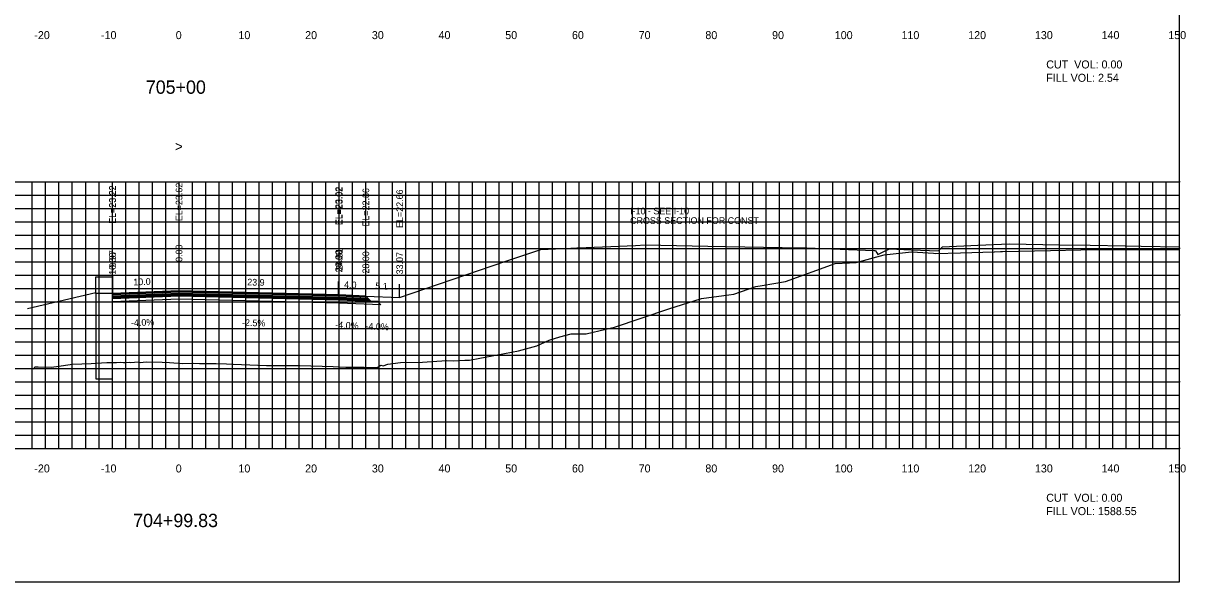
# Model space of a CAD drawing. Extents: x 1797518 to 1804843, y 248068 to 251132.
# Drawn here: x 1803287.6 to 1803461.9, y 250079.4 to 250163.2 of the extents above; entities that cross this region are included whole.
import ezdxf

# ---------------------------------------------------------------- set-up
doc = ezdxf.new("R2010")
doc.units = 0
for name, color, linetype in [('1', 7, 'Continuous'), ('10', 7, 'Continuous'), ('3', 7, 'Continuous'), ('4', 7, 'Continuous'), ('60', 7, 'Continuous'), ('ANNO-TXT', 7, 'Continuous'), ('BASE', 7, 'Continuous'), ('CL-CNST', 7, 'Continuous'), ('Level 62', 7, 'Continuous'), ('LOWER BINDER', 7, 'Continuous'), ('M-ROADS', 7, 'Continuous'), ('UPPER BINDER', 7, 'Continuous'), ('WEARING', 7, 'Continuous')]:
    doc.layers.add(name, color=color, linetype=linetype)

msp = doc.modelspace()

# ---------------------------------------------------------------- linework, layer by layer
for p, q in [((1803301, 250122.65), (1803301, 250124.65)), ((1803301.04, 250122.65), (1803301.04, 250124.65)), ((1803311, 250123.05), (1803311, 250125.05)), ((1803334.92, 250122.45), (1803334.92, 250124.45)), ((1803335, 250122.45), (1803335, 250124.45)), ((1803335.02, 250122.45), (1803335.02, 250124.45)), ((1803339, 250122.29), (1803339, 250124.29)), ((1803344.07, 250122.09), (1803344.07, 250124.09))]:
    msp.add_line(p, q)
msp.add_lwpolyline([(1803161, 250079.43), (1803461, 250079.43), (1803461, 250269.43), (1803161, 250269.43)], close=True)
at = {"layer": '3'}
msp.add_line((1803288.28, 250120.43), (1803298.5, 250122.82), dxfattribs=at)
at = {"layer": '60'}
for p, q in [((1803461, 250099.43), (1803461, 250139.43)), ((1803461.06, 250139.43), (1803461, 250139.43)), ((1803461.06, 250129.43), (1803461, 250129.43)), ((1803461.06, 250119.43), (1803461, 250119.43)), ((1803461.06, 250109.43), (1803461, 250109.43)), ((1803161, 250099.43), (1803461, 250099.43)), ((1803291, 250099.37), (1803291, 250099.43)), ((1803301, 250099.37), (1803301, 250099.43)), ((1803311, 250099.37), (1803311, 250099.43)), ((1803321, 250099.37), (1803321, 250099.43)), ((1803331, 250099.37), (1803331, 250099.43)), ((1803341, 250099.37), (1803341, 250099.43)), ((1803351, 250099.37), (1803351, 250099.43)), ((1803361, 250099.37), (1803361, 250099.43)), ((1803371, 250099.37), (1803371, 250099.43)), ((1803381, 250099.37), (1803381, 250099.43)), ((1803391, 250099.37), (1803391, 250099.43)), ((1803401, 250099.37), (1803401, 250099.43)), ((1803411, 250099.37), (1803411, 250099.43)), ((1803421, 250099.37), (1803421, 250099.43)), ((1803431, 250099.37), (1803431, 250099.43)), ((1803441, 250099.37), (1803441, 250099.43)), ((1803451, 250099.37), (1803451, 250099.43)), ((1803461, 250099.37), (1803461, 250099.43)), ((1803461.06, 250099.43), (1803461, 250099.43))]:
    msp.add_line(p, q, dxfattribs=at)
at = {"layer": 'BASE'}
msp.add_lwpolyline([(1803301, 250121.93), (1803311, 250122.33), (1803335, 250121.73), (1803339.75, 250121.54), (1803340.75, 250121.5), (1803341.27, 250120.98), (1803335, 250121.23), (1803311, 250121.83), (1803301, 250121.43)], close=True, dxfattribs=at)
at = {"layer": 'CL-CNST'}
for points in [[(1803344.07, 250122.09), (1803359.99, 250127.53), (1803365.24, 250129.28), (1803368.55, 250129.42), (1803368.77, 250129.43), (1803370.63, 250129.51), (1803370.79, 250129.52), (1803379.44, 250129.89), (1803380.89, 250129.95), (1803390.29, 250129.78), (1803393, 250129.73), (1803401.4, 250129.57), (1803405.11, 250129.5), (1803411.37, 250129.27), (1803415.21, 250129.13), (1803415.33, 250129.13), (1803415.42, 250129.13), (1803415.62, 250128.77), (1803415.75, 250128.52), (1803416.75, 250129), (1803417.48, 250129.35), (1803420.75, 250129.23), (1803424.89, 250129.08), (1803425.15, 250129.38), (1803425.43, 250129.69), (1803430.73, 250129.92), (1803435.51, 250130.13), (1803442.97, 250129.99), (1803447.59, 250129.9), (1803452.81, 250129.81), (1803455.21, 250129.76), (1803461, 250129.65)], [(1803301, 250122.65), (1803301.04, 250122.65), (1803311, 250123.05), (1803334.92, 250122.45), (1803335, 250122.45), (1803335.02, 250122.45), (1803339, 250122.29), (1803344.07, 250122.09)]]:
    msp.add_lwpolyline(points, dxfattribs=at)
for points in [[(1803301, 250122.65), (1803298.5, 250122.65), (1803298.5, 250125.15), (1803301, 250125.15)], [(1803298.5, 250109.87), (1803301, 250109.87), (1803301, 250122.65), (1803298.5, 250122.65)]]:
    msp.add_lwpolyline(points, close=True, dxfattribs=at)
at = {"layer": 'Level 62'}
for p, q in [((1803161, 250139.43), (1803461, 250139.43)), ((1803289, 250099.43), (1803289, 250139.43)), ((1803291, 250099.43), (1803291, 250139.43)), ((1803293, 250099.43), (1803293, 250139.43)), ((1803295, 250099.43), (1803295, 250139.43)), ((1803297, 250099.43), (1803297, 250139.43)), ((1803299, 250099.43), (1803299, 250139.43)), ((1803301, 250099.43), (1803301, 250139.43)), ((1803303, 250099.43), (1803303, 250139.43)), ((1803305, 250099.43), (1803305, 250139.43)), ((1803307, 250099.43), (1803307, 250139.43)), ((1803309, 250099.43), (1803309, 250139.43)), ((1803311, 250099.43), (1803311, 250139.43)), ((1803313, 250099.43), (1803313, 250139.43)), ((1803315, 250099.43), (1803315, 250139.43)), ((1803317, 250099.43), (1803317, 250139.43)), ((1803319, 250099.43), (1803319, 250139.43)), ((1803321, 250099.43), (1803321, 250139.43)), ((1803323, 250099.43), (1803323, 250139.43)), ((1803325, 250099.43), (1803325, 250139.43)), ((1803327, 250099.43), (1803327, 250139.43)), ((1803329, 250099.43), (1803329, 250139.43)), ((1803331, 250099.43), (1803331, 250139.43)), ((1803333, 250099.43), (1803333, 250139.43)), ((1803335, 250099.43), (1803335, 250139.43)), ((1803337, 250099.43), (1803337, 250139.43)), ((1803339, 250099.43), (1803339, 250139.43)), ((1803341, 250099.43), (1803341, 250139.43)), ((1803343, 250099.43), (1803343, 250139.43)), ((1803345, 250099.43), (1803345, 250139.43)), ((1803347, 250099.43), (1803347, 250139.43)), ((1803349, 250099.43), (1803349, 250139.43)), ((1803351, 250099.43), (1803351, 250139.43)), ((1803353, 250099.43), (1803353, 250139.43)), ((1803355, 250099.43), (1803355, 250139.43)), ((1803357, 250099.43), (1803357, 250139.43)), ((1803359, 250099.43), (1803359, 250139.43)), ((1803361, 250099.43), (1803361, 250139.43)), ((1803363, 250099.43), (1803363, 250139.43)), ((1803365, 250099.43), (1803365, 250139.43)), ((1803367, 250099.43), (1803367, 250139.43)), ((1803369, 250099.43), (1803369, 250139.43)), ((1803371, 250099.43), (1803371, 250139.43)), ((1803373, 250099.43), (1803373, 250139.43)), ((1803375, 250099.43), (1803375, 250139.43)), ((1803377, 250099.43), (1803377, 250139.43)), ((1803379, 250099.43), (1803379, 250139.43)), ((1803381, 250099.43), (1803381, 250139.43)), ((1803383, 250099.43), (1803383, 250139.43)), ((1803385, 250099.43), (1803385, 250139.43)), ((1803387, 250099.43), (1803387, 250139.43)), ((1803389, 250099.43), (1803389, 250139.43)), ((1803391, 250099.43), (1803391, 250139.43)), ((1803393, 250099.43), (1803393, 250139.43)), ((1803395, 250099.43), (1803395, 250139.43)), ((1803397, 250099.43), (1803397, 250139.43)), ((1803399, 250099.43), (1803399, 250139.43)), ((1803401, 250099.43), (1803401, 250139.43)), ((1803403, 250099.43), (1803403, 250139.43)), ((1803405, 250099.43), (1803405, 250139.43)), ((1803407, 250099.43), (1803407, 250139.43)), ((1803409, 250099.43), (1803409, 250139.43)), ((1803411, 250099.43), (1803411, 250139.43)), ((1803413, 250099.43), (1803413, 250139.43)), ((1803415, 250099.43), (1803415, 250139.43)), ((1803417, 250099.43), (1803417, 250139.43)), ((1803419, 250099.43), (1803419, 250139.43)), ((1803421, 250099.43), (1803421, 250139.43)), ((1803423, 250099.43), (1803423, 250139.43)), ((1803425, 250099.43), (1803425, 250139.43)), ((1803427, 250099.43), (1803427, 250139.43)), ((1803429, 250099.43), (1803429, 250139.43)), ((1803431, 250099.43), (1803431, 250139.43)), ((1803433, 250099.43), (1803433, 250139.43)), ((1803435, 250099.43), (1803435, 250139.43)), ((1803437, 250099.43), (1803437, 250139.43)), ((1803439, 250099.43), (1803439, 250139.43)), ((1803441, 250099.43), (1803441, 250139.43)), ((1803443, 250099.43), (1803443, 250139.43)), ((1803445, 250099.43), (1803445, 250139.43)), ((1803447, 250099.43), (1803447, 250139.43)), ((1803449, 250099.43), (1803449, 250139.43)), ((1803451, 250099.43), (1803451, 250139.43)), ((1803453, 250099.43), (1803453, 250139.43)), ((1803455, 250099.43), (1803455, 250139.43)), ((1803457, 250099.43), (1803457, 250139.43)), ((1803459, 250099.43), (1803459, 250139.43)), ((1803461, 250099.43), (1803461, 250139.43)), ((1803161, 250137.43), (1803461, 250137.43)), ((1803161, 250135.43), (1803461, 250135.43)), ((1803161, 250133.43), (1803461, 250133.43)), ((1803161, 250131.43), (1803461, 250131.43)), ((1803161, 250129.43), (1803461, 250129.43)), ((1803161, 250127.43), (1803461, 250127.43)), ((1803161, 250125.43), (1803461, 250125.43)), ((1803161, 250123.43), (1803461, 250123.43)), ((1803161, 250121.43), (1803461, 250121.43)), ((1803161, 250119.43), (1803461, 250119.43)), ((1803161, 250117.43), (1803461, 250117.43)), ((1803161, 250115.43), (1803461, 250115.43)), ((1803161, 250113.43), (1803461, 250113.43)), ((1803161, 250111.43), (1803461, 250111.43)), ((1803161, 250109.43), (1803461, 250109.43)), ((1803161, 250107.43), (1803461, 250107.43)), ((1803161, 250105.43), (1803461, 250105.43)), ((1803161, 250103.43), (1803461, 250103.43)), ((1803161, 250101.43), (1803461, 250101.43)), ((1803161, 250099.43), (1803461, 250099.43))]:
    msp.add_line(p, q, dxfattribs=at)
at = {"layer": 'LOWER BINDER'}
for points in [[(1803311, 250122.71), (1803335, 250122.11), (1803339.36, 250121.94), (1803339.55, 250121.74), (1803335, 250121.92), (1803311, 250122.52), (1803301, 250122.12), (1803301, 250122.31)], [(1803311, 250122.52), (1803335, 250121.92), (1803339.55, 250121.74), (1803339.75, 250121.54), (1803335, 250121.73), (1803311, 250122.33), (1803301, 250121.93), (1803301, 250122.12)]]:
    msp.add_lwpolyline(points, close=True, dxfattribs=at)
at = {"layer": 'M-ROADS'}
msp.add_lwpolyline([(1803286.71, 250111.41), (1803288.97, 250111.41), (1803289.11, 250111.38), (1803289.21, 250111.41), (1803289.29, 250111.46), (1803289.4, 250111.65), (1803289.49, 250111.66), (1803289.89, 250111.66), (1803291.82, 250111.64), (1803292.62, 250111.74), (1803295.01, 250112.06), (1803297.82, 250112.19), (1803300.18, 250112.34), (1803301.64, 250112.34), (1803302.25, 250112.38), (1803302.68, 250112.34), (1803302.94, 250112.34), (1803303.06, 250112.33), (1803303.53, 250112.36), (1803303.73, 250112.34), (1803304.92, 250112.4), (1803305.18, 250112.34), (1803306.09, 250112.4), (1803308.47, 250112.38), (1803309.56, 250112.31), (1803311.55, 250112.19), (1803313.19, 250112.2), (1803314.05, 250112.18), (1803314.86, 250112.17), (1803316.55, 250112.19), (1803318.11, 250112.11), (1803319.13, 250112.07), (1803321.63, 250111.97), (1803322.83, 250111.91), (1803324.12, 250111.86), (1803325.35, 250111.87), (1803326.66, 250111.87), (1803327.01, 250111.86), (1803329.13, 250111.86), (1803334.08, 250111.7), (1803336.02, 250111.62), (1803336.85, 250111.62), (1803338.37, 250111.61), (1803338.57, 250111.61), (1803338.77, 250111.61), (1803340.68, 250111.57), (1803341.23, 250111.93), (1803341.61, 250111.84), (1803342.3, 250112.08), (1803344.19, 250112.31), (1803347.48, 250112.39), (1803351.11, 250112.62), (1803352.18, 250112.59), (1803353.82, 250112.66), (1803354.18, 250112.66), (1803354.54, 250112.66), (1803356.11, 250112.96), (1803358.73, 250113.47), (1803361.87, 250114.07), (1803364.64, 250114.82), (1803366.47, 250115.69), (1803368.1, 250116.15), (1803369.79, 250116.63), (1803370.91, 250116.63), (1803372.02, 250116.63), (1803374.98, 250117.32), (1803376.26, 250117.62), (1803384.41, 250120.38), (1803389.33, 250121.92), (1803392.67, 250122.39), (1803394.16, 250122.59), (1803397.48, 250123.71), (1803398.4, 250123.87), (1803401.89, 250124.46), (1803409.38, 250127.15), (1803411.49, 250127.26), (1803412.52, 250127.32), (1803416.69, 250128.46), (1803420.78, 250128.9), (1803420.84, 250128.9), (1803420.9, 250128.9), (1803424.12, 250128.7), (1803424.4, 250128.66), (1803428.16, 250128.78), (1803433.18, 250128.93), (1803433.26, 250128.93), (1803434.15, 250128.96), (1803434.44, 250128.97), (1803441.62, 250129.12), (1803446.21, 250129.23), (1803449.59, 250129.25), (1803458.4, 250129.27), (1803458.99, 250129.26), (1803460.12, 250129.25), (1803461, 250129.24)], dxfattribs=at)
at = {"layer": 'UPPER BINDER'}
msp.add_lwpolyline([(1803339.36, 250121.94), (1803339.16, 250122.13), (1803335, 250122.3), (1803311, 250122.9), (1803301, 250122.5), (1803301, 250122.31), (1803311, 250122.71), (1803335, 250122.11)], close=True, dxfattribs=at)
at = {"layer": 'WEARING'}
msp.add_lwpolyline([(1803339.16, 250122.13), (1803339, 250122.29), (1803335, 250122.45), (1803311, 250123.05), (1803311, 250123.05), (1803301, 250122.65), (1803301, 250122.5), (1803311, 250122.9), (1803335, 250122.3)], close=True, dxfattribs=at)

# ---------------------------------------------------------------- texts
at = {"layer": '1'}
for s, p in [('705+00', (1803306.02, 250152.63)), ('704+99.83', (1803304.12, 250087.63))]:
    msp.add_text(s, height=2, dxfattribs=at).set_placement(p)
at = {"layer": '10'}
for s, p in [('-20', (1803289.3, 250160.83)), ('-10', (1803299.3, 250160.83)), ('0', (1803310.5, 250160.83)), ('10', (1803319.9, 250160.83)), ('20', (1803329.9, 250160.83)), ('30', (1803339.9, 250160.83)), ('40', (1803349.9, 250160.83)), ('50', (1803359.9, 250160.83)), ('60', (1803369.9, 250160.83)), ('70', (1803379.9, 250160.83)), ('80', (1803389.9, 250160.83)), ('90', (1803399.9, 250160.83)), ('100', (1803409.3, 250160.83)), ('110', (1803419.3, 250160.83)), ('120', (1803429.3, 250160.83)), ('130', (1803439.3, 250160.83)), ('140', (1803449.3, 250160.83)), ('150', (1803459.3, 250160.83)), ('-20', (1803289.3, 250095.83)), ('-10', (1803299.3, 250095.83)), ('0', (1803310.5, 250095.83)), ('10', (1803319.9, 250095.83)), ('20', (1803329.9, 250095.83)), ('30', (1803339.9, 250095.83)), ('40', (1803349.9, 250095.83)), ('50', (1803359.9, 250095.83)), ('60', (1803369.9, 250095.83)), ('70', (1803379.9, 250095.83)), ('80', (1803389.9, 250095.83)), ('90', (1803399.9, 250095.83)), ('100', (1803409.3, 250095.83)), ('110', (1803419.3, 250095.83)), ('120', (1803429.3, 250095.83)), ('130', (1803439.3, 250095.83)), ('140', (1803449.3, 250095.83)), ('150', (1803459.3, 250095.83))]:
    msp.add_text(s, height=1.2, dxfattribs=at).set_placement(p)
at = {"layer": '3'}
for s, p in [('EL=23.22', (1803301.5, 250133.12)), ('EL=23.22', (1803301.54, 250133.12)), ('EL=23.62', (1803311.5, 250133.52)), ('EL=23.02', (1803335.42, 250132.92)), ('EL=23.02', (1803335.5, 250132.92)), ('EL=23.02', (1803335.52, 250132.92)), ('EL=22.86', (1803339.5, 250132.72)), ('EL=22.66', (1803344.57, 250132.51)), ('-9.97', (1803301.54, 250126.1)), ('0.00', (1803311.5, 250127.41)), ('23.92', (1803335.42, 250125.9)), ('24.00', (1803335.5, 250125.82)), ('24.01', (1803335.52, 250126.15)), ('-10.00', (1803301.5, 250125.03)), ('28.00', (1803339.5, 250125.66)), ('33.07', (1803344.57, 250125.54))]:
    msp.add_text(s, height=1, rotation=90, dxfattribs=at).set_placement(p)
for s, p in [('I-10 - SEE I-10', (1803378.61, 250134.55)), ('CROSS SECTION FOR CONST ', (1803378.61, 250133.11))]:
    msp.add_text(s, height=1, dxfattribs=at).set_placement(p)
at = {"layer": '4'}
for s, rotation, p in [('10.0', 2.2906, (1803304.16, 250123.88)), ('23.9', 358.5689, (1803321.21, 250123.89)), ('4.0', 357.7094, (1803335.73, 250123.52)), ('5.1', 357.7094, (1803340.42, 250123.33)), ('-4.0%', 2.2906, (1803303.81, 250117.76)), ('-2.5%', 358.5689, (1803320.43, 250117.81)), ('-4.0%', 357.7094, (1803334.4, 250117.47)), ('-4.0%', 357.7094, (1803338.93, 250117.29))]:
    msp.add_text(s, height=1, rotation=rotation, dxfattribs=at).set_placement(p)
at = {"layer": '60'}
msp.add_text('>', height=1.5, dxfattribs=at).set_placement((1803310.39, 250143.99))
at = {"layer": 'ANNO-TXT'}
for s, p in [('CUT  VOL: 0.00', (1803441, 250156.43)), ('FILL VOL: 2.54', (1803441, 250154.43)), ('CUT  VOL: 0.00', (1803441, 250091.43)), ('FILL VOL: 1588.55', (1803441, 250089.43))]:
    msp.add_text(s, height=1.2, dxfattribs=at).set_placement(p)

doc.saveas('drawing.dxf')
